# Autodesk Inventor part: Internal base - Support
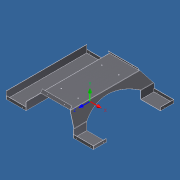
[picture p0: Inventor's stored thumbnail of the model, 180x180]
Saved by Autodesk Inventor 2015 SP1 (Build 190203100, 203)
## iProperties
Category: Mechanical Engineering Drawing and Design - CADD
Manager: Fábio Ricardo de Oliveira Souza
Company: SENAI - Serviço Nacional de Aprendizagem Industrial
Created: 2011-06
Part Number: Internal base - Support
Material: Steel
Description: Stainless Steel (Din- X6CrNiTi18-10)
Document SubType Name: Sheet Metal
Designer: Guilherme Augusto Franco de Souza
Engineer: George Geraldo de Oliveia Silva
Authority: Fábio Ricardo de Oliveira Soza
Density: 7.85 g/cm^3
Sheet Metal Rule: Default_mm
Flat Pattern Width: 89.1939 cm
Flat Pattern Length: 64.1335 cm
Flat Pattern Area: 5720.32 cm^2
Sheet Metal Width: 891,939 mm
Sheet Metal Length: 641,335 mm
Sheet Metal Area: 572032,008 mm^2
Mass: 6648.38 g
Surface Area: 8548.13 cm^2
Volume: 846.927 cm^3
Appearance: Machined 02
Subject: WorldSkill 2011 - London, England
Author: Guilherme Augusto Franco de Souza
Revision Number: 00
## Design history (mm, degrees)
sketch "Sketch1"
  geometry: L1 (-175, 0)-(-175, 60); L2 (-175, 60)-(-110, 125); L3 (-110, 125)-(110, 125); L4 (110, 125)-(175, 60); L5 (175, 60)-(175, 0); L6 (175, 0)-(323.5, 0); L7 (-175, 0)-(-323.5, 0); 2 further points
  constraints: 14 end point, 5 equal length, 2 horizontal alignment, 2 perpendicular, 1 midpoint, 1 vertical, 1 vertical alignment
  dimensions: "d0" = 125 distance from line of L3 L5.end; "d1" = 60 distance of L4.end L5.end; "d2" = 220 distance of L2.end L3.end; "d3" = 148.5 distance of L5.end L6.end; "d4" = 647 distance of L7.end L6.end
extrude_surface "ExtrusionSrf1" sketch "Sketch1" dims "d5" = 597, "d6" = 0
sketch "Sketch2"
  geometry: L1 (60, 298.5)-(125, 298.5) reference; L2 (55, 298.5)-(228.296, 198.448); L3 (125, -298.5)-(60, -298.5) reference; L4 (55, -298.5)-(228.296, -198.448); L5 (60.085, -298.5)-(260.19, -298.5); 1 further point
  constraints: 6 end point, 2 equal length, 2 point on line, 1 horizontal, 1 vertical alignment
  dimensions: "d7" = 30 deg angle of L1 L2; "d8" = 30 deg angle of L5 L4; "d104" = 55 horizontal distance of L2.start point (0, 0)
split "Split1"
split "Split2"
delete_face "Delete Face1"
sketch "Sketch3"
  geometry: L1 (0, 200)-(60, 200); L2 (0, -200)-(60, -200); L3 (0, -280)-(0, 280) reference; A1 r 440.667 centre (-332.667, 0) between (60, -200) and (60, 200); 1 further point
  constraints: 4 end point, 2 parallel, 2 point on circle, 1 centre point, 1 horizontal, 1 horizontal alignment, 1 vertical alignment
  dimensions: "d10" = 200 distance from line of point (0, 0) L1; "d11" = 400 distance between parallel lines of L2 L1 (= 2 x d10); "d12" = 108 distance edge to line of A1 L3; "d103" = 60 distance of L1.start L1.end
split "Split3" sketch "Sketch3"
delete_face "Delete Face2"
fillet "Fillet1" dims "d14" = 2 (= Thickness), "d16" = 2.5, "d47" = 2.5
thicken "Thicken1" dims "d15" = 2 (= Thickness)
node "Flange1"
node "Flange2"
node "Flange3"
node "Flange4"
sketch "Sketch9"
  geometry: L1 (0, -22.5)-(218.343, -22.5) reference; L2 (0, 0)-(218.343, 0) reference; L3 (46.672, -12.5)-(171.672, -12.5); 2 further points
  constraints: 2 end point, 1 horizontal alignment, 1 midpoint, 1 parallel, 1 vertical alignment
  dimensions: "d73" = 12.5 distance from line of L2 L3.start; "d74" = 125 distance of L3.end L3.start
hole "Hole1" sketch "Sketch9" at (46.672, -12.5), (171.672, -12.5) diameter "d76" = 3.3; stored, may be unused: countersink angle "d80" = 90 deg, drill point angle "d82" = 118 deg; dims "d77" = 6, "d78" = 4, "d79" = 2, "d81" = 2 (= Thickness)
mirror "Mirror1"
sketch "Sketch10"
  geometry: 5 further points
  constraints: 2 horizontal alignment, 2 vertical alignment
  dimensions: "d83" = 125 distance of point (171.672, 103.755) point (46.672, 103.755); "d84" = 62.5 horizontal distance of point (109.172, 253.755) point (171.672, 103.755) (= 0.5 x d83); "d85" = 150 vertical distance of point (109.172, 253.755) point (171.672, 103.755); "d86" = 300 distance of point (171.672, 103.755) point (171.672, 403.755) (= 2 x d85)
hole "Hole2" sketch "Sketch10" at (46.672, 403.755), (46.672, 103.755), (171.672, 103.755), (171.672, 403.755) diameter "d87" = 7; stored, may be unused: countersink angle "d91" = 90 deg, drill point angle "d93" = 118 deg; dims "d88" = 6, "d89" = 4, "d90" = 2, "d92" = 2 (= Thickness)
sketch "Sketch11"
  geometry: L1 (0, 22.5)-(-2.25, 22.5); L2 (-2.25, 22.5)-(-2.25, -2.5); L3 (-2.25, -2.5)-(0, -2.5); L4 (0, -2.5)-(0, 22.5); 1 further point
  constraints: 8 end point, 2 parallel, 1 horizontal, 1 perpendicular
  dimensions: "d100" = 2.25 distance of L2.end L3.end
extrude "Extrusion1" cut sketch "Sketch11" stored distance "d101" = 10; taper "d102" = 0 deg
mirror "Mirror2"
extrude_surface "ExtrusionSrf2" dims "d105" = 556, "d106" = 0
split "Split4"
extrude_surface "ExtrusionSrf3" dims "d107" = 556, "d108" = 0
split "Split5"
node "Hole4"
mirror "Mirror3"
node "Hole6"
mirror "Mirror4"
node "Hole8"
node "Hole10"
body "Solid1"
body "Srf1"
sketch "Sketch4"
  geometry: L1 through (0, -298.5) direction (0, 1); L2 through (-27.5, 0) direction (-1, 0); L3 (-55, 0)-(-55, -597); L4 (-55, -597)-(0, -597)
  constraints: 6 end point, 1 horizontal, 1 perpendicular, 1 vertical
face "Plate1" dims "d17" = 2 (= BendReliefWidth), "d18" = 1 (= BendReliefDepth), "d19" = 4 (= MinimumRemnant), "d20" = 2 (= BendRadius), "d21" = 55, "d22" = 90 deg, "d23" = 0.5 (= 0.25 x BendRadius), "d24" = 8 (= CornerReliefSize), "d25" = 2 (= GapSize), "d26" = 2 (= JacobiRadiusSize), "SeamGap" = 0.01, "Thickness" = 2 (derived)
bend "Bend1" dims "d17" = 2 (= BendReliefWidth), "d18" = 1 (= BendReliefDepth), "d19" = 4 (= MinimumRemnant), "d20" = 2 (= BendRadius), "d21" = 55, "d22" = 90 deg, "d23" = 0.5 (= 0.25 x BendRadius), "SeamGap" = 0.01, "Thickness" = 2 (derived)
feature "Corner1" dims "d21" = 55, "d22" = 90 deg, "d24" = 8 (= CornerReliefSize), "d25" = 2 (= GapSize), "d26" = 2 (= JacobiRadiusSize)
sketch "Sketch5"
  geometry: L1 through (-71.75, 0) direction (1, 0); L2 through (0, 12.5) direction (0, 1); L3 (0, 25)-(-143.5, 25); L4 (-143.5, 25)-(-143.5, 0)
  constraints: 6 end point, 1 horizontal, 1 perpendicular, 1 vertical
face "Plate2" dims "d27" = 2 (= BendReliefWidth), "d28" = 1 (= BendReliefDepth), "d29" = 4 (= MinimumRemnant), "d30" = 2 (= BendRadius), "d31" = 25, "d32" = 90 deg, "d33" = 0.5 (= 0.25 x BendRadius), "d34" = 8 (= CornerReliefSize), "d35" = 2 (= GapSize), "d36" = 2 (= JacobiRadiusSize), "SeamGap" = 0.01, "Thickness" = 2 (derived)
bend "Bend2" dims "d27" = 2 (= BendReliefWidth), "d28" = 1 (= BendReliefDepth), "d29" = 4 (= MinimumRemnant), "d30" = 2 (= BendRadius), "d31" = 25, "d32" = 90 deg, "d33" = 0.5 (= 0.25 x BendRadius), "SeamGap" = 0.01, "Thickness" = 2 (derived)
feature "Corner2" dims "d31" = 25, "d32" = 90 deg, "d34" = 8 (= CornerReliefSize), "d35" = 2 (= GapSize), "d36" = 2 (= JacobiRadiusSize)
sketch "Sketch6"
  geometry: L1 through (-73, 0) direction (1, 0); L2 through (0, 12.5) direction (0, 1); L3 (0, 25)-(-146, 25); L4 (-146, 25)-(-146, 0)
  constraints: 6 end point, 1 horizontal, 1 perpendicular, 1 vertical
face "Plate3" dims "d37" = 2 (= BendReliefWidth), "d38" = 1 (= BendReliefDepth), "d39" = 4 (= MinimumRemnant), "d40" = 2 (= BendRadius), "d41" = 25, "d42" = 90 deg, "d43" = 0.5 (= 0.25 x BendRadius), "d44" = 8 (= CornerReliefSize), "d45" = 2 (= GapSize), "d46" = 2 (= JacobiRadiusSize), "d49" = 10, "d50" = 10, "d51" = 0.5, "d52" = 0.5, "SeamGap" = 0.01, "Thickness" = 2 (derived)
bend "Bend3" dims "d37" = 2 (= BendReliefWidth), "d38" = 1 (= BendReliefDepth), "d39" = 4 (= MinimumRemnant), "d40" = 2 (= BendRadius), "d41" = 25, "d42" = 90 deg, "d43" = 0.5 (= 0.25 x BendRadius), "SeamGap" = 0.01, "Thickness" = 2 (derived)
feature "Corner3" dims "d41" = 25, "d42" = 90 deg, "d44" = 8 (= CornerReliefSize), "d45" = 2 (= GapSize), "d46" = 2 (= JacobiRadiusSize)
sketch "Sketch7"
  geometry: L1 through (109.172, 0) direction (-1, 0); L2 through (0, -13.415) direction (0, -1); L3 (0, -26.83)-(218.343, -26.83); L4 (218.343, -26.83)-(218.343, 0)
  constraints: 6 end point, 1 horizontal, 1 perpendicular, 1 vertical
face "Plate4" dims "d53" = 2 (= BendReliefWidth), "d54" = 1 (= BendReliefDepth), "d55" = 4 (= MinimumRemnant), "d56" = 2 (= BendRadius), "d57" = 25, "d58" = 120 deg, "d59" = 0.5 (= 0.25 x BendRadius), "d60" = 8 (= CornerReliefSize), "d61" = 2 (= GapSize), "d62" = 2 (= JacobiRadiusSize), "SeamGap" = 0.01, "Thickness" = 2 (derived)
bend "Bend4" dims "d53" = 2 (= BendReliefWidth), "d54" = 1 (= BendReliefDepth), "d55" = 4 (= MinimumRemnant), "d56" = 2 (= BendRadius), "d57" = 25, "d58" = 120 deg, "d59" = 0.5 (= 0.25 x BendRadius), "SeamGap" = 0.01, "Thickness" = 2 (derived)
feature "Corner4" dims "d57" = 25, "d58" = 120 deg, "d60" = 8 (= CornerReliefSize), "d61" = 2 (= GapSize), "d62" = 2 (= JacobiRadiusSize)
body "Srf2"
body "Srf3"
sketch "Sketch12"
  geometry: 4 further points
hole "Hole3" sketch "Sketch12" diameter "d113" = 3.4; stored, may be unused: countersink angle "d117" = 90 deg, drill point angle "d119" = 0 deg; dims "d114" = 6, "d115" = 4, "d116" = 2, "d118" = 8
sketch "Sketch13"
  geometry: 1 further point
hole "Hole5" sketch "Sketch13" diameter "d120" = 3.4; stored, may be unused: countersink angle "d124" = 90 deg, drill point angle "d126" = 0 deg; dims "d121" = 6, "d122" = 4, "d123" = 2, "d125" = 8
sketch "Sketch14"
  geometry: 2 further points
hole "Hole7" sketch "Sketch14" diameter "d127" = 3.4; stored, may be unused: countersink angle "d131" = 90 deg, drill point angle "d133" = 0 deg; dims "d128" = 6, "d129" = 4, "d130" = 2, "d132" = 8
sketch "Sketch15"
  geometry: 2 further points
hole "Hole9" sketch "Sketch15" diameter "d134" = 3.4; stored, may be unused: countersink angle "d138" = 90 deg, drill point angle "d140" = 0 deg; dims "d135" = 6, "d136" = 4, "d137" = 2, "d139" = 8
feature "Definition1"
other parameters: "BendRadius" = 2 (= Thickness), "BendReliefWidth" = 2 (= Thickness), "BendReliefDepth" = 1 (= 0.5 x Thickness), "CornerReliefSize" = 8 (= 4 x Thickness), "MinimumRemnant" = 4 (= 2 x Thickness), "TransitionRadius" = 2 (= BendRadius), "JacobiRadiusSize" = 2 (= BendRadius), "GapSize" = 2 (= Thickness), "d94" = 0, "d95" = 0, "d96" = 0, "d97" = 0, "d98" = 0, "d99" = 0, "BendRadius" = 2, "BendReliefDepth" = 1, "BendReliefWidth" = 2, "CornerReliefSize" = 8, "GapSize" = 2, "JacobiRadiusSize" = 2, "MinimumRemnant" = 4, "Thickness" = 2, "TransitionRadius" = 2
